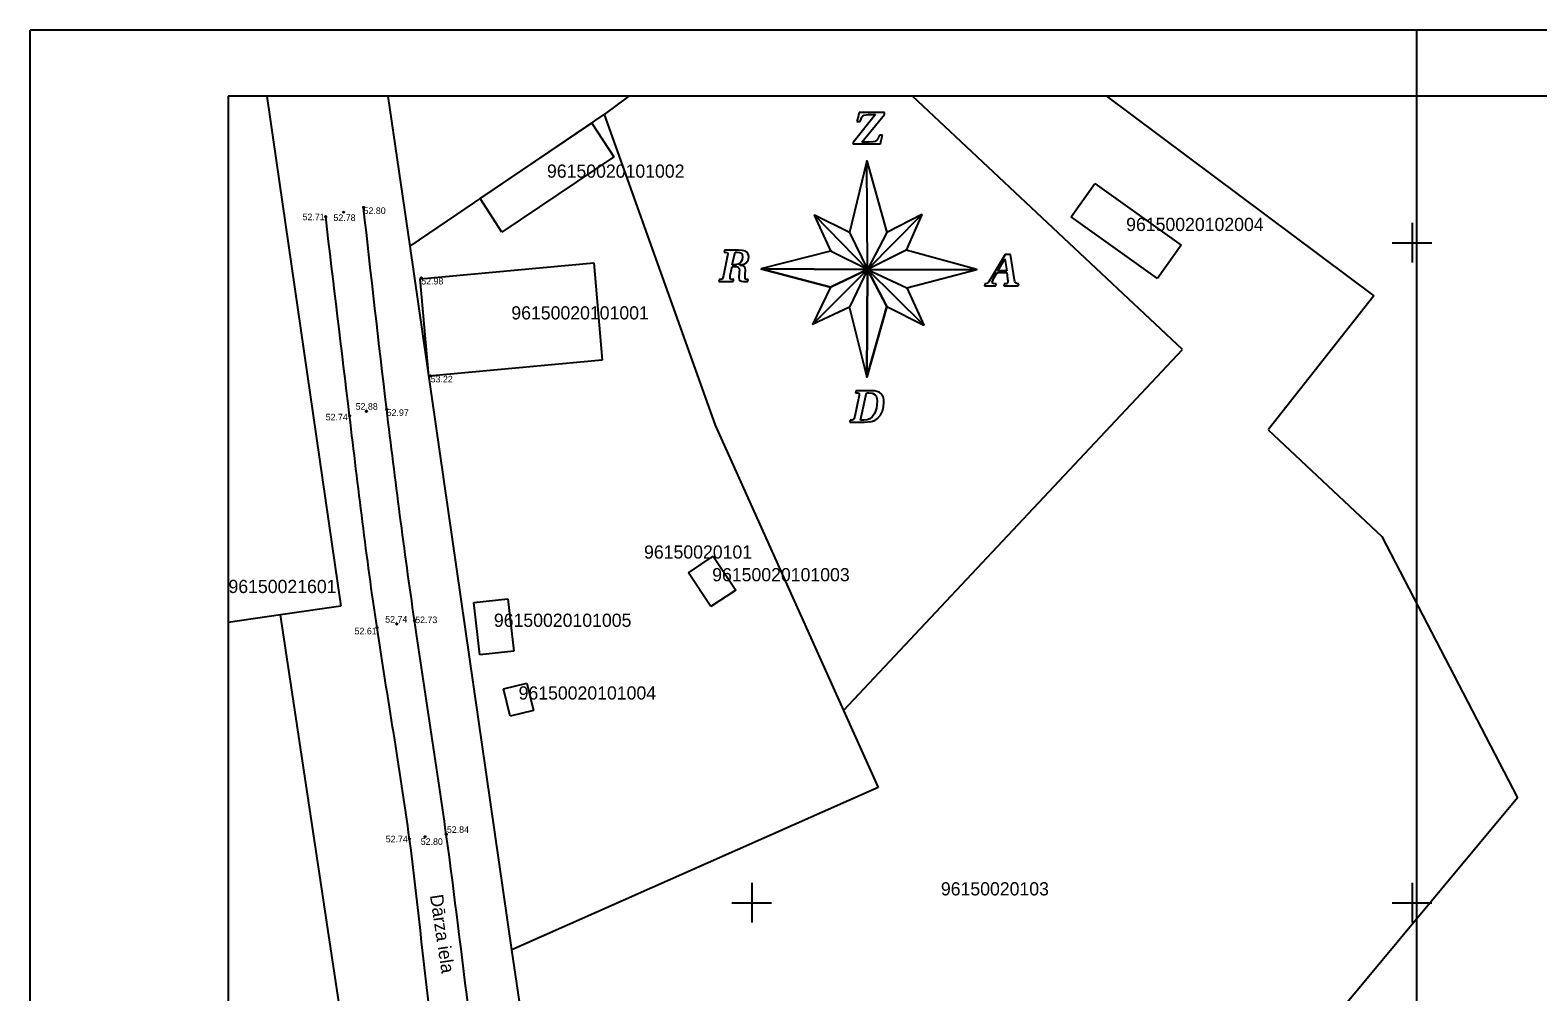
# Model space of a CAD drawing. Extents: x 578395 to 578590, y 418519 to 418816.
# Drawn here: x 578395.4 to 578509.5, y 418743.2 to 418816.1 of the extents above; entities that cross this region are included whole.
import ezdxf

# ---------------------------------------------------------------- set-up
doc = ezdxf.new("R2010")
doc.units = 0
for name, color, linetype in [('BUVE_EKAS_UZMR_####_#', 7, 'Continuous'), ('BUVE_EKAS_UZMR_TKST_#', 7, 'Continuous'), ('BUVE_EKAS_VEKT_####_#', 7, 'Continuous'), ('BUVE_EKAS_VEKT_TKST_#', 7, 'Continuous'), ('CELI_CMAL_####_####_#', 7, 'Continuous'), ('CELI_IELA_####_TKST_#', 7, 'Continuous'), ('GEOD_ELEM_####_####_#', 7, 'Continuous'), ('RAMI_PLAN_####_TKST_#', 7, 'Continuous'), ('RELJ_AATZ_####_TKST_#', 7, 'Continuous'), ('RELJ_ELEM_####_####_#', 7, 'Continuous'), ('ROBZ_UZMR_####_####_#', 7, 'Continuous'), ('ROBZ_UZMR_####_TKST_#', 7, 'Continuous')]:
    doc.layers.add(name, color=color, linetype=linetype)

msp = doc.modelspace()

# ---------------------------------------------------------------- linework, layer by layer
at = {"layer": 'BUVE_EKAS_UZMR_####_#'}
for p, q in [((578429.44, 418803.36), (578437.89, 418809.06)), ((578437.89, 418809.06), (578439.54, 418806.51)), ((578439.54, 418806.51), (578431.08, 418800.81)), ((578431.08, 418800.81), (578429.44, 418803.36)), ((578424.89, 418797.27), (578438.03, 418798.49)), ((578438.03, 418798.49), (578438.68, 418791.11)), ((578425.55, 418789.89), (578424.89, 418797.27)), ((578438.68, 418791.11), (578425.55, 418789.89)), ((578428.95, 418772.74), (578431.53, 418773.02)), ((578429.41, 418768.77), (578428.95, 418772.74)), ((578431.53, 418773.02), (578431.99, 418769.05)), ((578431.99, 418769.05), (578429.41, 418768.77))]:
    msp.add_line(p, q, dxfattribs=at)
at = {"layer": 'BUVE_EKAS_VEKT_####_#'}
for p, q in [((578474.18, 418801.96), (578475.98, 418804.48)), ((578475.98, 418804.48), (578482.52, 418799.81)), ((578480.72, 418797.3), (578474.18, 418801.96)), ((578482.52, 418799.81), (578480.72, 418797.3)), ((578445.2, 418775), (578447.08, 418776.25)), ((578447.08, 418776.25), (578448.79, 418773.69)), ((578446.91, 418772.44), (578445.2, 418775)), ((578448.79, 418773.69), (578446.91, 418772.44)), ((578431.2, 418766.2), (578432.96, 418766.64)), ((578432.96, 418766.64), (578433.47, 418764.57)), ((578431.71, 418764.13), (578431.2, 418766.2)), ((578433.47, 418764.57), (578431.71, 418764.13))]:
    msp.add_line(p, q, dxfattribs=at)
at = {"layer": 'CELI_CMAL_####_####_#'}
for points in [[(578428.55, 418677.14), (578430.48, 418675.63), (578430.57, 418675.83), (578431.34, 418682.76), (578430.86, 418698.21), (578428.95, 418714.66), (578427.16, 418730.13), (578425.7, 418740.98), (578424.08, 418754.82), (578421.62, 418770.83), (578419.54, 418786.89), (578417.73, 418801.98)], [(578540.02, 418586.37), (578525.99, 418597.85), (578512.59, 418608.64), (578501.67, 418618.24), (578486.37, 418629.74), (578473.85, 418639.53), (578461.4, 418649.85), (578445.48, 418664.31), (578434.89, 418671.62), (578433.59, 418673.24), (578433.71, 418674.57), (578434.34, 418682.51), (578433.83, 418698.67), (578431.51, 418715.15), (578429.96, 418730.38), (578428.63, 418741.31), (578426.86, 418755.17), (578424.46, 418771.37), (578422.35, 418787.38), (578420.6, 418802.68)]]:
    msp.add_spline(points, degree=3, dxfattribs=at)
at = {"layer": 'GEOD_ELEM_####_####_#'}
for p, q in [((578500, 418801.5), (578500, 418800)), ((578498.5, 418800), (578500, 418800)), ((578500, 418800), (578500, 418798.5)), ((578500, 418800), (578501.5, 418800)), ((578450, 418751.5), (578450, 418750)), ((578500, 418751.5), (578500, 418750)), ((578448.5, 418750), (578450, 418750)), ((578450, 418750), (578450, 418748.5)), ((578450, 418750), (578451.5, 418750)), ((578498.5, 418750), (578500, 418750)), ((578500, 418750), (578500, 418748.5)), ((578500, 418750), (578501.5, 418750))]:
    msp.add_line(p, q, dxfattribs=at)
at = {"layer": 'RAMI_PLAN_####_TKST_#'}
for p, q in [((578395.35, 418667.61), (578395.35, 418816.11)), ((578590.35, 418816.11), (578395.35, 418816.11)), ((578500.35, 418667.61), (578500.35, 418816.11)), ((578459.38, 418809.71), (578457.67, 418807.6)), ((578458.13, 418809.86), (578458.08, 418809.64)), ((578460.06, 418809.86), (578458.13, 418809.86)), ((578458.34, 418807.63), (578460.04, 418809.73)), ((578458.42, 418809.6), (578458.52, 418809.66)), ((578458.52, 418809.66), (578458.65, 418809.7)), ((578458.65, 418809.7), (578458.8, 418809.71)), ((578458.8, 418809.71), (578459.38, 418809.71)), ((578460.04, 418809.73), (578460.06, 418809.86)), ((578458.08, 418809.64), (578457.96, 418809.19)), ((578457.96, 418809.19), (578458.21, 418809.19)), ((578458.21, 418809.19), (578458.34, 418809.51)), ((578458.34, 418809.51), (578458.42, 418809.6)), ((578457.67, 418807.6), (578457.65, 418807.49)), ((578457.65, 418807.49), (578459.74, 418807.49)), ((578458.88, 418807.63), (578458.34, 418807.63)), ((578459.18, 418807.65), (578458.88, 418807.63)), ((578459.35, 418807.68), (578459.18, 418807.65)), ((578459.5, 418807.81), (578459.35, 418807.68)), ((578459.63, 418808.06), (578459.5, 418807.81)), ((578459.66, 418808.15), (578459.63, 418808.06)), ((578459.91, 418808.15), (578459.66, 418808.15)), ((578459.74, 418807.49), (578459.79, 418807.74)), ((578459.79, 418807.74), (578459.91, 418808.15)), ((578462.88, 418802.14), (578460.22, 418800.79)), ((578447.93, 418799.43), (578447.9, 418799.29)), ((578448.48, 418799.43), (578447.93, 418799.43)), ((578449, 418799.43), (578448.48, 418799.43)), ((578449.3, 418799.41), (578449, 418799.43)), ((578449.52, 418799.36), (578449.3, 418799.41)), ((578448.17, 418799.04), (578447.85, 418797.52)), ((578447.9, 418799.29), (578447.96, 418799.29)), ((578447.96, 418799.29), (578448.13, 418799.26)), ((578448.13, 418799.26), (578448.17, 418799.22)), ((578448.17, 418799.22), (578448.18, 418799.15)), ((578448.18, 418799.15), (578448.17, 418799.04)), ((578448.52, 418798.34), (578448.73, 418799.29)), ((578448.79, 418798.34), (578448.52, 418798.34)), ((578448.73, 418799.29), (578448.91, 418799.29)), ((578448.98, 418798.38), (578448.79, 418798.34)), ((578448.91, 418799.29), (578449.09, 418799.27)), ((578449.15, 418798.51), (578448.98, 418798.38)), ((578449.09, 418799.27), (578449.21, 418799.21)), ((578449.13, 418798.32), (578449.39, 418798.38)), ((578449.13, 418798.29), (578449.13, 418798.32)), ((578449.31, 418798.27), (578449.13, 418798.29)), ((578449.26, 418798.7), (578449.15, 418798.51)), ((578449.21, 418799.21), (578449.27, 418799.11)), ((578449.3, 418798.93), (578449.26, 418798.7)), ((578449.27, 418799.11), (578449.3, 418798.93)), ((578449.43, 418798.21), (578449.31, 418798.27)), ((578449.39, 418798.38), (578449.58, 418798.49)), ((578449.63, 418799.29), (578449.52, 418799.36)), ((578449.58, 418798.49), (578449.66, 418798.57)), ((578449.71, 418799.19), (578449.63, 418799.29)), ((578449.66, 418798.57), (578449.72, 418798.67)), ((578449.75, 418799.07), (578449.71, 418799.19)), ((578449.72, 418798.67), (578449.76, 418798.79)), ((578449.77, 418798.93), (578449.75, 418799.07)), ((578449.76, 418798.79), (578449.77, 418798.93)), ((578456.06, 418799.38), (578450.68, 418798.03)), ((578469.18, 418799.11), (578468.11, 418797.3)), ((578468.62, 418797.88), (578469.16, 418798.79)), ((578469.16, 418798.79), (578469.31, 418797.88)), ((578469.59, 418799.11), (578469.18, 418799.11)), ((578469.89, 418797.2), (578469.59, 418799.11)), ((578447.53, 418797.21), (578447.5, 418797.07)), ((578447.67, 418797.22), (578447.53, 418797.21)), ((578447.75, 418797.25), (578447.67, 418797.22)), ((578447.8, 418797.34), (578447.75, 418797.25)), ((578447.85, 418797.52), (578447.8, 418797.34)), ((578448.35, 418797.33), (578448.37, 418797.51)), ((578448.36, 418797.26), (578448.35, 418797.33)), ((578448.41, 418797.23), (578448.36, 418797.26)), ((578448.37, 418797.51), (578448.52, 418798.2)), ((578448.64, 418797.21), (578448.41, 418797.23)), ((578448.52, 418798.2), (578448.68, 418798.2)), ((578448.6, 418797.07), (578448.64, 418797.21)), ((578448.68, 418798.2), (578448.85, 418798.19)), ((578448.85, 418798.19), (578448.96, 418798.15)), ((578448.96, 418798.15), (578449.04, 418798.06)), ((578449.02, 418797.5), (578449.01, 418797.37)), ((578449.01, 418797.37), (578449.04, 418797.23)), ((578449.04, 418797.67), (578449.02, 418797.5)), ((578449.04, 418798.06), (578449.06, 418797.91)), ((578449.05, 418797.79), (578449.04, 418797.67)), ((578449.04, 418797.23), (578449.1, 418797.13)), ((578449.06, 418797.91), (578449.05, 418797.79)), ((578449.1, 418797.13), (578449.21, 418797.08)), ((578449.51, 418798.09), (578449.43, 418798.21)), ((578449.49, 418797.39), (578449.51, 418797.63)), ((578449.5, 418797.31), (578449.49, 418797.39)), ((578449.53, 418797.25), (578449.5, 418797.31)), ((578449.53, 418797.9), (578449.51, 418798.09)), ((578449.51, 418797.63), (578449.53, 418797.9)), ((578449.6, 418797.22), (578449.53, 418797.25)), ((578449.72, 418797.21), (578449.6, 418797.22)), ((578449.7, 418797.07), (578449.72, 418797.21)), ((578450.68, 418798.03), (578458.77, 418797.98)), ((578455.95, 418796.63), (578450.68, 418798.03)), ((578454.59, 418793.82), (578458.77, 418797.98)), ((578458.77, 418797.98), (578455.95, 418796.63)), ((578458.77, 418797.98), (578457.41, 418795.12)), ((578458.71, 418789.81), (578458.77, 418797.98)), ((578458.77, 418797.98), (578460.22, 418795.17)), ((578468.11, 418797.3), (578467.93, 418797.02)), ((578468.2, 418797.01), (578468.27, 418797.2)), ((578468.27, 418797.2), (578468.36, 418797.36)), ((578468.36, 418797.36), (578468.59, 418797.74)), ((578468.59, 418797.74), (578469.31, 418797.74)), ((578469.31, 418797.88), (578468.62, 418797.88)), ((578469.31, 418797.74), (578469.37, 418797.28)), ((578469.37, 418797.28), (578469.39, 418797.14)), ((578469.39, 418797.14), (578469.39, 418797.03)), ((578469.92, 418797.06), (578469.89, 418797.2)), ((578447.5, 418797.07), (578448.05, 418797.07)), ((578448.05, 418797.07), (578448.6, 418797.07)), ((578449.21, 418797.08), (578449.36, 418797.07)), ((578449.36, 418797.07), (578449.7, 418797.07)), ((578455.95, 418796.63), (578454.59, 418793.82)), ((578467.65, 418796.89), (578467.62, 418796.74)), ((578467.62, 418796.74), (578468.04, 418796.74)), ((578467.81, 418796.92), (578467.65, 418796.89)), ((578467.93, 418797.02), (578467.81, 418796.92)), ((578468.04, 418796.74), (578468.47, 418796.74)), ((578468.22, 418796.95), (578468.2, 418797.01)), ((578468.27, 418796.91), (578468.22, 418796.95)), ((578468.5, 418796.89), (578468.27, 418796.91)), ((578468.47, 418796.74), (578468.5, 418796.89)), ((578469.11, 418796.89), (578469.08, 418796.74)), ((578469.08, 418796.74), (578469.63, 418796.74)), ((578469.3, 418796.9), (578469.11, 418796.89)), ((578469.37, 418796.94), (578469.3, 418796.9)), ((578469.39, 418797.03), (578469.37, 418796.94)), ((578469.63, 418796.74), (578470.18, 418796.74)), ((578469.96, 418796.97), (578469.92, 418797.06)), ((578470.06, 418796.91), (578469.96, 418796.97)), ((578470.21, 418796.89), (578470.06, 418796.91)), ((578470.18, 418796.74), (578470.21, 418796.89)), ((578457.41, 418795.12), (578454.59, 418793.82)), ((578457.41, 418795.06), (578458.71, 418789.81)), ((578460.22, 418795.17), (578458.71, 418789.81)), ((578458.11, 418788.32), (578457.79, 418786.87)), ((578457.89, 418788.78), (578457.85, 418788.64)), ((578457.85, 418788.64), (578458.08, 418788.62)), ((578458.42, 418788.78), (578457.89, 418788.78)), ((578458.08, 418788.62), (578458.13, 418788.58)), ((578458.13, 418788.43), (578458.11, 418788.32)), ((578458.13, 418788.58), (578458.14, 418788.5)), ((578458.14, 418788.5), (578458.13, 418788.43)), ((578459.04, 418788.78), (578458.42, 418788.78)), ((578458.53, 418787.95), (578458.69, 418788.64)), ((578458.69, 418788.64), (578458.86, 418788.64)), ((578458.86, 418788.64), (578459.15, 418788.6)), ((578459.28, 418788.77), (578459.04, 418788.78)), ((578459.15, 418788.6), (578459.34, 418788.49)), ((578459.48, 418788.73), (578459.28, 418788.77)), ((578459.34, 418788.49), (578459.41, 418788.41)), ((578459.41, 418788.41), (578459.45, 418788.3)), ((578459.45, 418788.3), (578459.48, 418788.17)), ((578459.64, 418788.67), (578459.48, 418788.73)), ((578459.48, 418788.17), (578459.49, 418788.02)), ((578459.49, 418788.02), (578459.48, 418787.73)), ((578459.77, 418788.59), (578459.64, 418788.67)), ((578459.87, 418788.48), (578459.77, 418788.59)), ((578459.95, 418788.32), (578459.87, 418788.48)), ((578459.99, 418788.13), (578459.95, 418788.32)), ((578460.01, 418787.9), (578459.99, 418788.13)), ((578457.79, 418786.87), (578457.74, 418786.69)), ((578458.23, 418786.56), (578458.38, 418787.25)), ((578458.38, 418787.25), (578458.53, 418787.95)), ((578459.27, 418787.02), (578459.12, 418786.82)), ((578459.37, 418787.23), (578459.27, 418787.02)), ((578459.44, 418787.47), (578459.37, 418787.23)), ((578459.48, 418787.73), (578459.44, 418787.47)), ((578459.53, 418786.68), (578459.74, 418786.93)), ((578459.74, 418786.93), (578459.9, 418787.24)), ((578459.9, 418787.24), (578459.98, 418787.56)), ((578459.98, 418787.56), (578460.01, 418787.9)), ((578457.45, 418786.56), (578457.42, 418786.41)), ((578457.42, 418786.41), (578457.97, 418786.41)), ((578457.61, 418786.57), (578457.45, 418786.56)), ((578457.7, 418786.6), (578457.61, 418786.57)), ((578457.74, 418786.69), (578457.7, 418786.6)), ((578457.97, 418786.41), (578458.5, 418786.41)), ((578458.48, 418786.56), (578458.23, 418786.56)), ((578458.73, 418786.58), (578458.48, 418786.56)), ((578458.5, 418786.41), (578459.05, 418786.45)), ((578458.94, 418786.67), (578458.73, 418786.58)), ((578459.12, 418786.82), (578458.94, 418786.67)), ((578459.05, 418786.45), (578459.31, 418786.53)), ((578459.31, 418786.53), (578459.53, 418786.68))]:
    msp.add_line(p, q, dxfattribs=at)
for points in [[(578410.35, 418811.11), (578410.35, 418524.11), (578585.35, 418524.11), (578585.35, 418811.11)], [(578458.71, 418806.2), (578457.41, 418800.79), (578458.77, 418797.98)], [(578467.05, 418797.98), (578461.68, 418799.44), (578458.77, 418797.98)], [(578450.68, 418798.03), (578455.95, 418796.63), (578458.77, 418797.98)], [(578458.77, 418797.98), (578458.71, 418789.81), (578460.22, 418795.17)]]:
    msp.add_lwpolyline(points, close=True, dxfattribs=at)
for points in [[(578458.71, 418806.2), (578460.22, 418800.79), (578458.77, 418797.98), (578458.71, 418806.2), (578457.41, 418800.79), (578458.77, 418797.98)], [(578457.41, 418800.79), (578454.75, 418802.09), (578458.77, 418797.98), (578456, 418799.33), (578454.75, 418802.09)], [(578458.77, 418797.98), (578462.88, 418802.14), (578461.68, 418799.44)], [(578461.74, 418796.58), (578467.05, 418797.98), (578461.68, 418799.44), (578458.77, 418797.98), (578467.05, 418797.98)], [(578460.22, 418795.17), (578463.04, 418793.77), (578458.77, 418797.98), (578461.74, 418796.58), (578463.04, 418793.77)]]:
    msp.add_lwpolyline(points, dxfattribs=at)
at = {"layer": 'RELJ_ELEM_####_####_#'}
for centre in [(578417.73, 418801.98), (578419.1, 418802.32), (578420.6, 418802.68), (578424.97, 418797.34), (578425.68, 418789.92), (578419.54, 418786.89), (578420.81, 418787.22), (578422.35, 418787.38), (578421.62, 418770.83), (578423.12, 418771.11), (578424.46, 418771.37), (578424.08, 418754.82), (578425.26, 418755), (578426.86, 418755.17)]:
    msp.add_circle(centre, 0.05, dxfattribs=at)
at = {"layer": 'ROBZ_UZMR_####_####_#'}
for p, q in [((578413.27, 418811.11), (578418.89, 418772.46)), ((578424.12, 418799.74), (578422.47, 418811.11)), ((578440.7, 418811.11), (578438.82, 418809.73)), ((578482.62, 418791.91), (578462.17, 418811.11)), ((578476.85, 418811.11), (578497.1, 418795.97)), ((578424.12, 418799.74), (578438.82, 418809.73)), ((578438.82, 418809.73), (578447.23, 418786.19)), ((578431.84, 418746.43), (578424.12, 418799.74)), ((578497.1, 418795.97), (578489.11, 418785.82)), ((578456.94, 418764.56), (578482.62, 418791.91)), ((578447.23, 418786.19), (578456.94, 418764.56)), ((578489.11, 418785.82), (578497.71, 418777.74)), ((578497.71, 418777.74), (578507.98, 418757.95)), ((578418.89, 418772.46), (578414.31, 418771.8)), ((578414.31, 418771.8), (578410.35, 418771.22)), ((578426.39, 418691.61), (578414.31, 418771.8)), ((578456.94, 418764.56), (578459.56, 418758.73)), ((578459.56, 418758.73), (578431.84, 418746.43)), ((578507.98, 418757.95), (578489.92, 418736.22)), ((578435.64, 418720.21), (578431.84, 418746.43))]:
    msp.add_line(p, q, dxfattribs=at)

# ---------------------------------------------------------------- texts
at = {"layer": 'BUVE_EKAS_UZMR_TKST_#'}
for s, p in [('96150020101002', (578434.49, 418804.93)), ('96150020101001', (578431.79, 418794.19)), ('96150020101005', (578430.47, 418770.9))]:
    msp.add_text(s, height=1, dxfattribs=at).set_placement(p)
at = {"layer": 'BUVE_EKAS_VEKT_TKST_#'}
for s, p in [('96150020102004', (578478.35, 418800.89)), ('96150020101003', (578447, 418774.35)), ('96150020101004', (578432.34, 418765.39))]:
    msp.add_text(s, height=1, dxfattribs=at).set_placement(p)
at = {"layer": 'CELI_IELA_####_TKST_#'}
msp.add_text('Dārza iela', height=1, rotation=278.5673, dxfattribs=at).set_placement((578425.62, 418750.55))
at = {"layer": 'RELJ_AATZ_####_TKST_#'}
for s, p in [('52.71', (578415.98, 418801.71)), ('52.78', (578418.32, 418801.65)), ('52.80', (578420.6, 418802.18)), ('52.98', (578424.97, 418796.84)), ('53.22', (578425.68, 418789.42)), ('52.74', (578417.73, 418786.54)), ('52.88', (578420, 418787.35)), ('52.97', (578422.35, 418786.88)), ('52.74', (578422.24, 418771.22)), ('52.73', (578424.51, 418771.18)), ('52.61', (578419.92, 418770.33)), ('52.74', (578422.28, 418754.57)), ('52.80', (578424.93, 418754.38)), ('52.84', (578426.91, 418755.29))]:
    msp.add_text(s, height=0.5, dxfattribs=at).set_placement(p)
at = {"layer": 'ROBZ_UZMR_####_TKST_#'}
for s, p in [('96150020101', (578441.84, 418776.07)), ('96150021601', (578410.37, 418773.46)), ('96150020103', (578464.32, 418750.55))]:
    msp.add_text(s, height=1, dxfattribs=at).set_placement(p)

doc.saveas('drawing.dxf')
